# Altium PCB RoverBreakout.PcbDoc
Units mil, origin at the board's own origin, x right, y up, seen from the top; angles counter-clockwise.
Board outline 6000 x 4000 mil, 2 copper layers (Top Layer, Bottom Layer); 28 components, 22 nets, 160 pads, 0 vias.
Unrouted connection lines stored in the file: 70.
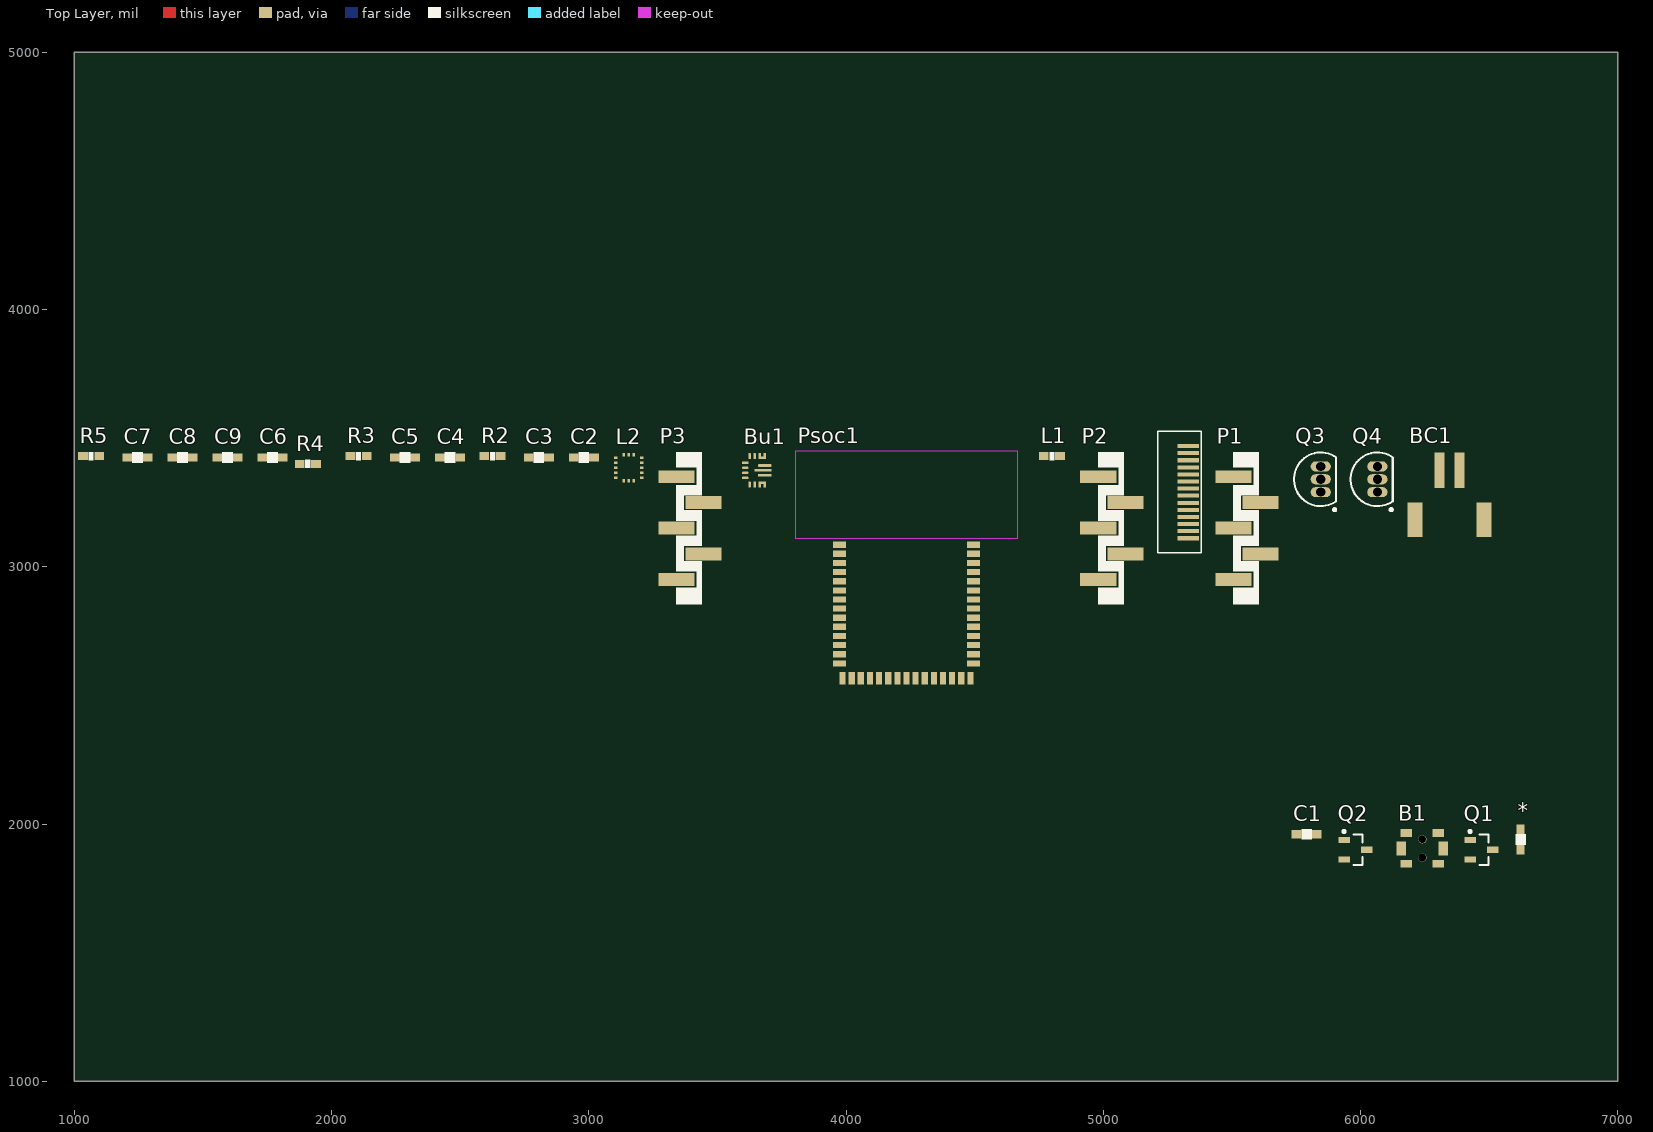
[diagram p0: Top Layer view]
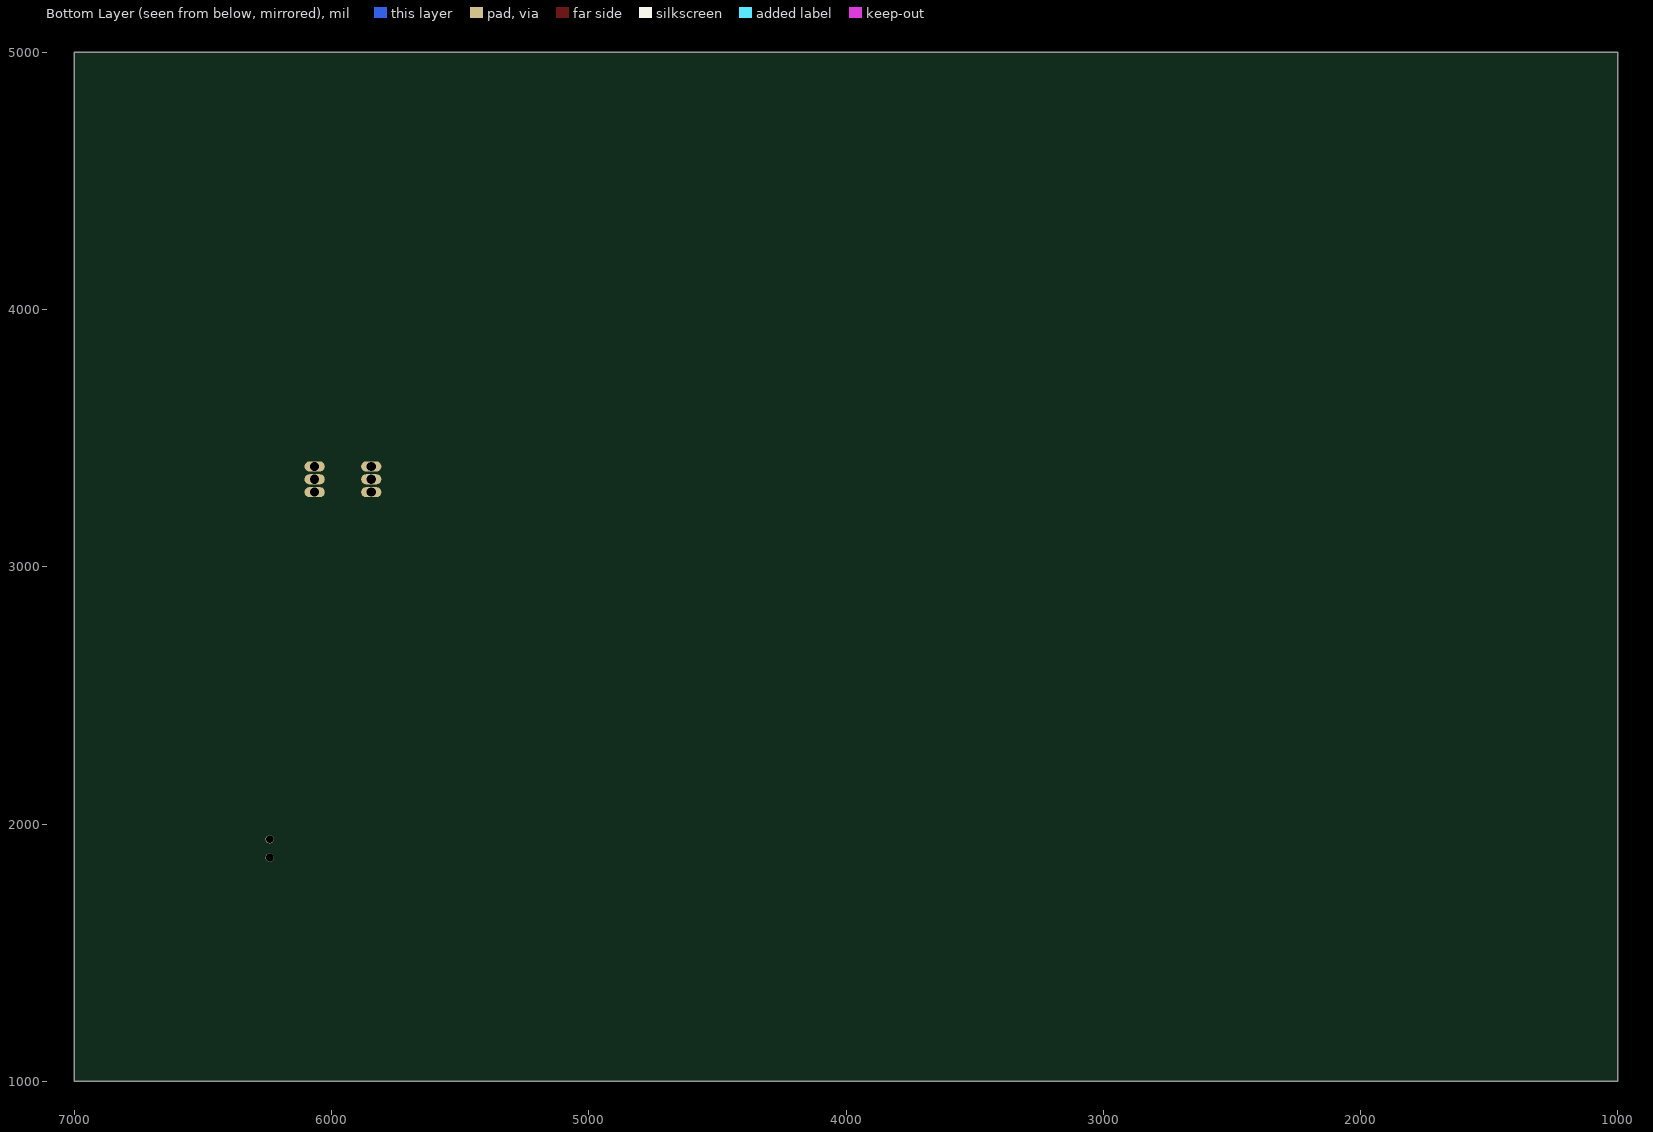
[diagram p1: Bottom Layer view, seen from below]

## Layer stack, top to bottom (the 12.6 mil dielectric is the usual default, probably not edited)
Top Solder: solder mask 0.4, Solder Resist, Dk 3.5
Top Layer: signal copper 1.4
Dielectric 1: dielectric 12.6, FR-4, Dk 4.8
Bottom Layer: signal copper 1.4
Bottom Solder: solder mask 0.4, Solder Resist, Dk 3.5

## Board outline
1000,1000 7000,1000 7000,5000 1000,5000

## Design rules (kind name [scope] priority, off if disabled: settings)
BoardOutlineClearance [All] p1: gap=16 ignorepadtopadclearanceinfootprint=FALSE except(0: Arc-SplitContinuation Track-SplitContinuation SMDPad-SplitContinuation THPad-SplitContinuation Via-SplitContinuation Fill-SplitContinuation Poly-SplitContinuation Region-SplitContinuation Text-SplitContinuation)
Clearance [All] p1: gap=6 ignorepadtopadclearanceinfootprint=FALSE
HoleSize [All] p1: absolutevalues=TRUE maxlimit=245 minlimit=12 maxpercent=80.000 minpercent=20.000
MinimumSolderMaskSliver [All] p1 off: minsoldermaskwidth=10
NetAntennae [All] p1 off: netantennaetolerance=0
PolygonConnect [All] p1: connectstyle=Relief reliefconductorwidth=10 reliefentries=4 polygonreliefangle="90 Angle" airgapwidth=10
RoutingVias [All] p1: holewidth=12 width=24 viastyle="Through Hole" minholewidth=6 minwidth=12 maxholewidth=23.62 maxwidth=47.24
SilkToSilkClearance [All] p1 off: silktosilkclearance=10
SilkToSolderMaskClearance [IsPad] p1 off: minsilkscreentomaskgap=10 clearancetoexposedcopper=TRUE
SolderMaskExpansion [All] p1: expansion=4 istentingtop=FALSE
Width [All] p1: maxlimit=78.74 minlimit=6 preferedwidth=6 minimp=50.000000 maximp=50.000000 favimp=50.000000
25 further rules are at their usual default settings.

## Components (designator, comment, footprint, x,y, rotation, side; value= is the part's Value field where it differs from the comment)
* "Motor" Motor 16575.63,51625 r90 top
B1 "Button" BUTTON 6240.63,1905 r0 top
BC1 "BatteryConnector" JST-Right-Angle-Connector-Team-7 6385.63,3375 r0 top
Bu1 "Buck_Boost_Converter" Buck_Boost_Converter 3650.63,3375 r0 top
C1 "Capacitor1" PASSIVE-CAPACITOR-0603 5790.63,1960 r0 top value=10uf
C2 "Passive-Capacitor-0603" PASSIVE-CAPACITOR-0603 2980.63,3425 r0 top
C3 "Capacitor1" PASSIVE-CAPACITOR-0603 2805.63,3425 r0 top value=10uF
C4 "Capacitor1" PASSIVE-CAPACITOR-0603 2460.63,3425 r0 top value=10uF
C5 "Capacitor1" PASSIVE-CAPACITOR-0603 2285.63,3425 r0 top value=10uF
C6 "Capacitor1" PASSIVE-CAPACITOR-0603 1770.63,3425 r0 top value=10uF
C7 "Capacitor1" PASSIVE-CAPACITOR-0603 1245.63,3425 r0 top value=22uF
C8 "Capacitor1" PASSIVE-CAPACITOR-0603 1420.63,3425 r0 top value=22uF
C9 "Capacitor1" PASSIVE-CAPACITOR-0603 1595.63,3425 r0 top value=22uF
L1 "Inductor" PASSIVE-INDUCTOR-0603 4800.63,3430 r0 top value=10uH
L2 "LGA-13" LIS3DH 3155.63,3385 r0 top
P1 "Connector-5pin" CONNECTOR-HEADER-PINS 5505.63,3150 r90 top
P2 "Connector-5pin" CONNECTOR-HEADER-PINS 4980.63,3150 r90 top
P3 "Connector-5pin" CONNECTOR-HEADER-PINS 3340.63,3150 r90 top
Psoc1 "PSoC 63 BLE" "PSoC-63 BLE" 4510.63,3280 r0 top
Q1 "PNP" SOT-23B_N 6470.63,1900 r0 top
Q2 "PNP" SOT-23B_N 5980.63,1900 r0 top
Q3 "NPN" TO-226-AA 5845.63,3340 r0 top
Q4 "NPN" TO-226-AA 6065.63,3340 r0 top
R2 "Resistor" PASSIVE-RESISTOR-0603 2625.63,3430 r0 top value=10k
R3 "Resistor" PASSIVE-RESISTOR-0603 2105.63,3430 r0 top value=470k
R4 "Resistor" PASSIVE-RESISTOR-0603 1907.64,3400 r0 top value=100k
R5 "Resistor" PASSIVE-RESISTOR-0603 1065.63,3430 r0 top value=150k
? "SSD1306" SSD1306 5330.63,3290 r90 top

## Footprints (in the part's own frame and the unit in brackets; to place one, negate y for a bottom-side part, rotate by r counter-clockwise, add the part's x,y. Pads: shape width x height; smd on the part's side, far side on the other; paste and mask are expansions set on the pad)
Buck_Boost_Converter [mm] "Buck Boost Converter"
  rrect50% 0.25x0.6 smd: EN(-0.15,1.4) FB(-0.65,-1.4) FB2(-0.15,-1.4) VIN(0.35,1.4) VIN(0.85,1.4) VOUT(0.35,-1.4) VOUT(0.85,-1.4) VSEL(-0.65,1.4)
  rrect50% 0.6x0.25 smd: GND(-1.075,-0.75) PG(-1.075,0.25) VAUX(-1.075,-0.25)
  rrect50% 1.35x0.25 smd: L1(0.85,0.475) L2(0.85,-0.475)
  rrect50% 1.7x0.25 smd: PGND(0.675,0)
  rect 0.6x0.25 smd: PS/S(-1.075,0.75)
  rrect50% 0.75x0.25 smd: VIN(0.6,1.225) VOUT(0.6,-1.225)
  body extent -1.07,-1.43 1.28,1.4, height 0.4
BUTTON [mm]
  round 0.8 hole 0.762 mask+0: 5(0,-0.9) 5(0,0.9)
  round 0.8 on Top Paste: 6(0.07,-0.653)
  rect 0.95x1.4 smd: B1(-2.075,0) B3(2.075,0)
  rect 1.15x0.75 smd: B2_0(1.575,-1.525) B2_1(-1.575,-1.525) B4_0(-1.575,1.525) B4_1(1.575,1.525)
CONNECTOR-HEADER-PINS [mm]
  rect 1.27x3.56 smd: 1(-5.08,0) 2(-2.54,-2.67) 3(0,0) 4(2.54,-2.67) 5(5.08,0)
  silkscreen extent -7.5,-2.5 7.5,0
JST-Right-Angle-Connector-Team-7 [mm]
  rect 1x3.5 smd: P1(-2,0) P2(0,0)
  rect 1.5x3.4 smd: Shield(-4.4,-4.9) Shield(2.4,-4.9)
  body extent -5.2,-8.1 2.8,1.9, height 5.7
LIS3DH [mm]
  rect 0.25x0.35 smd: ADC1(-0.5,1.275) ADC2(0,1.275) CS(0.5,-1.275) SDA/SDI/SDO(-0.5,-1.275) SDO/SA0(0,-1.275) VDD(0.5,1.275)
  rect 0.35x0.25 smd: ADC3(1.275,1) GND(-1.275,-1) GND(1.275,0.5) INT1(1.275,0) INT2(1.275,-1) NC(-1.275,0) NC(-1.275,0.5) RES(1.275,-0.5) SCL/SPC(-1.275,-0.5) VDDIO(-1.275,1)
  body extent -1.5,-1.5 1.5,1.5, height 0.25
Motor [mm]
  rect 0.965x0.8 smd: 1(-1263,252.8) 2(-1261,252.8)
  silkscreen extent -1262.5,252.3 -1261.5,253.3
PASSIVE-CAPACITOR-0603 [mm]
  rect 0.965x0.8 smd: 1(-1,0) 2(1,0)
  silkscreen extent -0.5,-0.5 0.5,0.5
PASSIVE-INDUCTOR-0603 [mm] "Inductor"
  rect 0.965x0.8 smd: 1(-0.8,0) 2(0.8,0)
  silkscreen extent -0.23,-0.4 0.23,0.4, body extent -0.82,-0.4 0.8,0.4, height 0.4
PASSIVE-RESISTOR-0603 [mm]
  rect 0.965x0.8 smd: 1(-0.8,0) 2(0.8,0)
  silkscreen extent -0.23,-0.4 0.23,0.4, body extent -0.82,-0.4 0.8,0.4, height 0.4
"PSoC-63 BLE" [mm]
  rect 1.27x0.61 smd: 1(-0.38,-4.93) 2(-0.38,-5.83) 3(-0.38,-6.73) 4(-0.38,-7.63) 5(-0.38,-8.54) 6(-0.38,-9.44) 7(-0.38,-10.34) 8(-0.38,-11.24) 9(-0.38,-12.14) 10(-0.38,-13.04) 11(-0.38,-13.95) 12(-0.38,-14.85) 13(-0.38,-15.75) 14(-0.38,-16.65) 30(-13.62,-16.65) 31(-13.62,-15.75) 32(-13.62,-14.85) 33(-13.62,-13.95) 34(-13.62,-13.04) 35(-13.62,-12.14) 36(-13.62,-11.24) 37(-13.62,-10.34) 38(-13.62,-9.44) 39(-13.62,-8.54) 40(-13.62,-7.63) 41(-13.62,-6.73) 42(-13.62,-5.83) 43(-13.62,-4.93)
  rect 0.61x1.27 smd: 15(-0.69,-18.12) 16(-1.59,-18.12) 17(-2.49,-18.12) 18(-3.39,-18.12) 19(-4.29,-18.12) 20(-5.2,-18.12) 21(-6.1,-18.12) 22(-7,-18.12) 23(-7.9,-18.12) 24(-8.8,-18.12) 25(-9.7,-18.12) 26(-10.61,-18.12) 27(-11.51,-18.12) 28(-12.41,-18.12) 29(-13.31,-18.12)
  Top Layer keep-out region: -18,-4.31 4,-4.31 4,4.31 -18,4.31
  body extent -14,-18.5 0,0, height 1.2
SOT-23B_N [mm] "SOT23, 3-Leads, Body 2.9x1.3mm, Pitch 0.95mm, Lead Span 2.4mm, IPC Medium Density"
  rect 1.15x0.6 smd: 1(-1.125,0.95) 2(-1.125,-0.95) 3(1.125,0)
  silkscreen extent -1.25,-1.5 0.7,1.92, body extent -0.7,-1.5 0.7,1.5, height 1.14
SSD1306 [mm]
  rect 0.4x2.1 smd: 1(-4.55,0) 2(-3.85,0) 3(-3.15,0) 4(-2.45,0) 5(-1.75,0) 6(-1.05,0) 7(-0.35,0) 8(0.35,0) 9(1.05,0) 10(1.75,0) 11(2.45,0) 12(3.15,0) 13(3.85,0) 14(4.55,0)
  silkscreen extent -6,-1.3 6,3
TO-226-AA [mm] "TO, Flat Index; 3 In-Line, Axial Leads; Body Dia. 4.8mm; Leads 0.55 x 0.51 mm (max)"
  oval 2x1 hole 0.9: 1(0,-1.27) 2(0,0) 3(0,1.27)
  silkscreen extent -2.65,-3.13 1.52,2.65, body extent -2.65,-2.66 1.52,2.66, height 5.33

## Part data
Q1 Q2: "PNP Bipolar Transistor"
Q3 Q4: "NPN Bipolar Transistor"
R2 R3 R4 R5: library part Resistor1
?: "SSD1306 OLED 0.9 Display Pmodâ„¢ Platform Evaluation Expansion Board", Package=None

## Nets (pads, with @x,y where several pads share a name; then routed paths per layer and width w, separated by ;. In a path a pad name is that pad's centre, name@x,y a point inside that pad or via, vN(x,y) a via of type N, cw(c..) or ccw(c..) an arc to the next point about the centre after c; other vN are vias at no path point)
EN: Bu1.EN Bu1.PS/S P3.1 P3.2 R2.1
FB: Bu1.FB P2.4 R3.1 R5.2
GND: BC1.P2 BC1.Shield Bu1.FB2 Bu1.GND Bu1.PGND Bu1.VSEL C1.1 C2.1 C3.1 C4.1 C5.1 C6.1 C7.1 C8.1 C9.1 L2.GND P2.1 Psoc1.1 Q3.3 Q4.3 R5.1
INT1: L2.INT1 P1.3
Net*_1: *.1 Q2.1 Q3.1
Net*_2: *.2 Q1.1 Q4.1
NetB1_B3: B1.B3 BC1.P1 C1.2
NetBu1_L1: Bu1.L1 L1.1
NetBu1_L2: Bu1.L2 L1.2
NetBu1_VAUX: Bu1.VAUX C2.2
NetC10_2: 
NetPS_1: 
NetPS_3: Q1.3 Q2.3
PG: Bu1.PG P2.5 R4.1
SCL: ?.10 L2.SCL/SPC P1.4 Psoc1.24
SDA: ?.11 L2.SDA/SDI/SDO P1.5 Psoc1.29
Vbackup: P1.2 Psoc1.3
Vbase1: Psoc1.14 Q1.2 Q4.2
Vbase2: Psoc1.9 Q2.2 Q3.2
VBat: ?.5 B1.B1 Bu1.VIN C3.2 C4.2 C5.2 P1.1 R2.2
Vout1: Bu1.VOUT C6.2 C7.2 C8.2 C9.2 L2.VDD L2.VDDIO P2.3 Psoc1.4 R3.2 R4.2
VSolar: P2.2
pads on no net: ?.1 ?.2 ?.3 ?.4 ?.6 ?.7 ?.8 ?.9 ?.12 ?.13 ?.14 B1.5 B1.6 B1.B2_0 B1.B2_1 B1.B4_0 B1.B4_1 L2.ADC1 L2.ADC2 L2.ADC3 L2.CS L2.INT2 L2.NC L2.RES L2.SDO/SA0 P3.3 P3.4 P3.5 Psoc1.2 Psoc1.5 Psoc1.6 Psoc1.7 Psoc1.8 Psoc1.10 Psoc1.11 Psoc1.12 Psoc1.13 Psoc1.15 Psoc1.16 Psoc1.17 Psoc1.18 Psoc1.19 Psoc1.20 Psoc1.21 Psoc1.22 Psoc1.23 Psoc1.25 Psoc1.26 Psoc1.27 Psoc1.28 Psoc1.30 Psoc1.31 Psoc1.32 Psoc1.33 Psoc1.34 Psoc1.35 Psoc1.36 Psoc1.37 Psoc1.38 Psoc1.39 Psoc1.40 Psoc1.41 Psoc1.42 Psoc1.43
